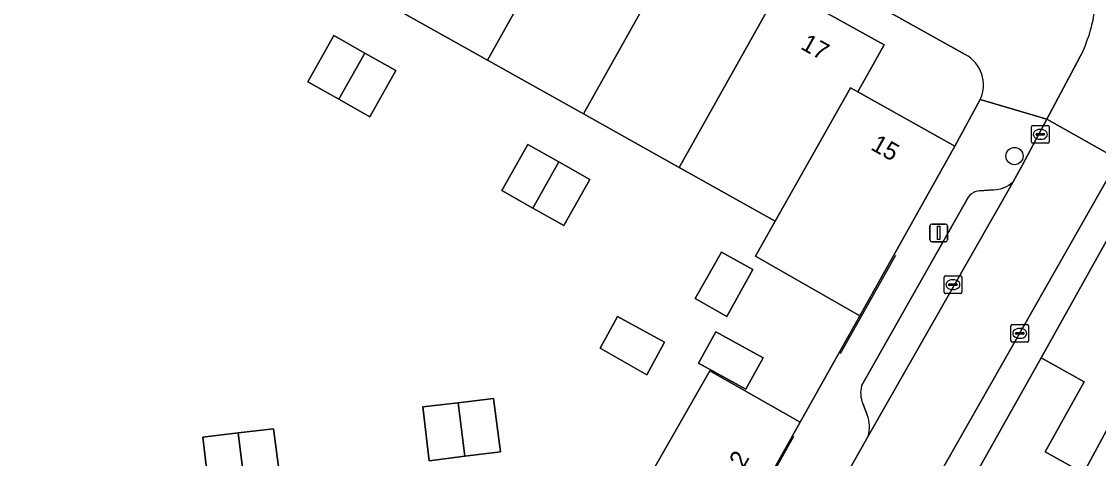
# Model space of a CAD drawing. Extents: x 163147 to 163550, y 380933 to 381639.
# Drawn here: x 163352.5 to 163413.5, y 381516.7 to 381541.5 of the extents above; entities that cross this region are included whole.
import ezdxf

# ---------------------------------------------------------------- set-up
doc = ezdxf.new("R2010")
doc.units = 0
for name, color, linetype in [('IMGEO_Boom', 7, 'Continuous'), ('IMGEO_Erf', 7, 'Continuous'), ('IMGEO_Groenvoorziening', 7, 'Continuous'), ('IMGEO_Kolk', 7, 'Continuous'), ('IMGEO_Lichtmast', 7, 'Continuous'), ('IMGEO_Muur', 7, 'Continuous'), ('IMGEO_Pand', 7, 'Continuous'), ('IMGEO_Pand_nummerreeks', 7, 'Continuous'), ('IMGEO_Parkeervlak_open', 7, 'Continuous'), ('IMGEO_Rijbaan_lokaal_open', 7, 'Continuous'), ('IMGEO_Voetpad_open', 7, 'Continuous')]:
    doc.layers.add(name, color=color, linetype=linetype)

msp = doc.modelspace()

# ---------------------------------------------------------------- linework, layer by layer
at = {"layer": 'IMGEO_Boom'}
msp.add_circle((163408.762, 381533.873), 0.489, dxfattribs=at)
at = {"layer": 'IMGEO_Erf'}
for points in [[(163389.772, 381533.219), (163384.335, 381536.26), (163378.897, 381539.301), (163373.46, 381542.342), (163368.022, 381545.383), (163362.584, 381548.424), (163357.147, 381551.465), (163351.494, 381554.627), (163344.686, 381558.434), (163341.996, 381559.951), (163335.192, 381563.765), (163329.483, 381566.965), (163323.994, 381570.042), (163318.505, 381573.12), (163313.016, 381576.197), (163307.526, 381579.274), (163306.339, 381577.158), (163301.172, 381580.046), (163302.358, 381582.169), (163302.037, 381582.351), (163296.548, 381585.428), (163291.473, 381588.273)], [(163290.692, 381502.077), (163296.934, 381502.909), (163303.175, 381503.742), (163309.37, 381504.568), (163317.378, 381505.636), (163320.439, 381506.043), (163328.504, 381507.143), (163334.606, 381507.974), (163340.83, 381508.823), (163347.054, 381509.671), (163353.278, 381510.52), (163359.502, 381511.368), (163365.726, 381512.217), (163371.951, 381513.065), (163378.25, 381513.924), (163378.437, 381512.446), (163386.81, 381513.506), (163391.494, 381521.713), (163396.616, 381518.793), (163399.995, 381524.821), (163394.095, 381528.2), (163395.21, 381530.178), (163389.772, 381533.219)], [(163412.675, 381515.904), (163410.492, 381517.121), (163412.7, 381521.08), (163410.272, 381522.434), (163405.156, 381513.335)]]:
    msp.add_lwpolyline(points, dxfattribs=at)
for points in [[(163368.718, 381538.086), (163370.193, 381540.698), (163371.952, 381539.705), (163373.711, 381538.712), (163372.236, 381536.1), (163370.477, 381537.093)], [(163381.187, 381534.535), (163382.946, 381533.542), (163384.705, 381532.549), (163383.23, 381529.937), (163381.471, 381530.93), (163379.712, 381531.923)], [(163392.157, 381528.422), (163393.933, 381527.438), (163392.466, 381524.79), (163390.677, 381525.803)], [(163386.277, 381524.781), (163388.941, 381523.333), (163387.936, 381521.476), (163385.288, 381522.981)], [(163390.856, 381522.148), (163391.845, 381523.923), (163394.528, 381522.435), (163393.543, 381520.66)], [(163377.237, 381519.9), (163379.244, 381520.135), (163379.639, 381517.124), (163377.621, 381516.869), (163375.602, 381516.613), (163375.235, 381519.665)], [(163364.781, 381518.185), (163366.788, 381518.42), (163367.183, 381515.409), (163365.165, 381515.154), (163363.146, 381514.898), (163362.779, 381517.95)]]:
    msp.add_lwpolyline(points, close=True, dxfattribs=at)
at = {"layer": 'IMGEO_Groenvoorziening'}
for points in [[(163405.961, 381539.624), (163371.092, 381559.098), (163297.645, 381600.322)], [(163349.497, 381567.024), (163356.3, 381563.209), (163357.48, 381562.547), (163358.512, 381564.182), (163362.881, 381561.73), (163362.519, 381561.082), (163367.958, 381558.033), (163373.393, 381554.987), (163378.828, 381551.941), (163384.263, 381548.895), (163389.698, 381545.85), (163395.133, 381542.804), (163396.436, 381542.073), (163396.812, 381542.714), (163401.373, 381540.169), (163399.878, 381537.517), (163405.373, 381534.442), (163406.822, 381537.075)]]:
    msp.add_lwpolyline(points, dxfattribs=at)
msp.add_arc((163405.063, 381537.901), 1.943, 334.8576, 62.47023, dxfattribs=at)
at = {"layer": 'IMGEO_Kolk'}
for p, q in [((163409.724, 381534.676), (163409.724, 381535.528)), ((163409.799, 381535.602), (163410.651, 381535.602)), ((163410.212, 381535.382), (163410.237, 381535.382)), ((163410.725, 381535.528), (163410.725, 381534.676)), ((163409.983, 381535.096), (163409.983, 381535.108)), ((163410.421, 381535.059), (163410.023, 381535.059)), ((163410.026, 381535.145), (163410.424, 381535.145)), ((163410.235, 381534.822), (163410.21, 381534.822)), ((163410.467, 381535.108), (163410.467, 381535.096)), ((163410.651, 381534.602), (163409.799, 381534.602)), ((163404.772, 381526.162), (163404.772, 381527.014)), ((163404.847, 381527.088), (163405.699, 381527.088)), ((163405.26, 381526.868), (163405.285, 381526.868)), ((163405.773, 381527.014), (163405.773, 381526.162)), ((163405.031, 381526.582), (163405.031, 381526.594)), ((163405.469, 381526.545), (163405.071, 381526.545)), ((163405.074, 381526.631), (163405.472, 381526.631)), ((163405.283, 381526.308), (163405.258, 381526.308)), ((163405.515, 381526.594), (163405.515, 381526.582)), ((163405.699, 381526.088), (163404.847, 381526.088)), ((163408.561, 381523.401), (163408.561, 381524.253)), ((163408.636, 381524.327), (163409.488, 381524.327)), ((163408.82, 381523.821), (163408.82, 381523.833)), ((163409.258, 381523.784), (163408.86, 381523.784)), ((163408.863, 381523.87), (163409.261, 381523.87)), ((163409.049, 381524.107), (163409.074, 381524.107)), ((163409.304, 381523.833), (163409.304, 381523.821)), ((163409.562, 381524.253), (163409.562, 381523.401)), ((163409.488, 381523.327), (163408.636, 381523.327)), ((163409.072, 381523.547), (163409.047, 381523.547))]:
    msp.add_line(p, q, dxfattribs=at)
for points in [[(163409.724, 381534.676), (163409.724, 381535.528)], [(163409.799, 381535.602), (163410.651, 381535.602)], [(163410.725, 381535.528), (163410.725, 381534.676)], [(163410.651, 381534.602), (163409.799, 381534.602)], [(163404.772, 381526.162), (163404.772, 381527.014)], [(163404.847, 381527.088), (163405.699, 381527.088)], [(163405.773, 381527.014), (163405.773, 381526.162)], [(163405.699, 381526.088), (163404.847, 381526.088)], [(163408.561, 381523.401), (163408.561, 381524.253)], [(163408.636, 381524.327), (163409.488, 381524.327)], [(163409.562, 381524.253), (163409.562, 381523.401)], [(163409.488, 381523.327), (163408.636, 381523.327)]]:
    msp.add_lwpolyline(points, dxfattribs=at)
for centre, radius, start, end in [((163409.801, 381535.526), 0.0765, 91.55205, 178.44795), ((163409.801, 381535.526), 0.0765, 91.55205, 178.44795), ((163410.649, 381535.526), 0.0765, 1.55205, 88.44795), ((163410.649, 381535.526), 0.0765, 1.55205, 88.44795), ((163410.023, 381535.105), 0.0403, 85.87752, 175.75265), ((163410.02, 381535.095), 0.0366, 178.93798, 274.71019), ((163410.424, 381535.102), 0.043, 264.86636, 352.45326), ((163410.428, 381535.107), 0.0386, 1.73085, 96.63898), ((163409.801, 381534.678), 0.0765, 181.55205, 268.44795), ((163409.801, 381534.678), 0.0765, 181.55205, 268.44795), ((163410.649, 381534.678), 0.0765, 271.55205, 358.44795), ((163410.649, 381534.678), 0.0765, 271.55205, 358.44795), ((163404.849, 381527.012), 0.0765, 91.55205, 178.44795), ((163404.849, 381527.012), 0.0765, 91.55205, 178.44795), ((163405.697, 381527.012), 0.0765, 1.55205, 88.44795), ((163405.697, 381527.012), 0.0765, 1.55205, 88.44795), ((163405.071, 381526.591), 0.0403, 85.87752, 175.75265), ((163405.068, 381526.581), 0.0366, 178.93798, 274.71019), ((163405.472, 381526.588), 0.043, 264.86636, 352.45326), ((163405.476, 381526.593), 0.0386, 1.73085, 96.63898), ((163404.849, 381526.164), 0.0765, 181.55205, 268.44795), ((163404.849, 381526.164), 0.0765, 181.55205, 268.44795), ((163405.697, 381526.164), 0.0765, 271.55205, 358.44795), ((163405.697, 381526.164), 0.0765, 271.55205, 358.44795), ((163408.638, 381524.251), 0.0765, 91.55205, 178.44795), ((163408.638, 381524.251), 0.0765, 91.55205, 178.44795), ((163408.86, 381523.83), 0.0403, 85.87752, 175.75265), ((163408.857, 381523.82), 0.0366, 178.93798, 274.71019), ((163409.261, 381523.827), 0.043, 264.86636, 352.45326), ((163409.265, 381523.832), 0.0386, 1.73085, 96.63898), ((163409.486, 381524.251), 0.0765, 1.55205, 88.44795), ((163409.486, 381524.251), 0.0765, 1.55205, 88.44795), ((163408.638, 381523.403), 0.0765, 181.55205, 268.44795), ((163408.638, 381523.403), 0.0765, 181.55205, 268.44795), ((163409.486, 381523.403), 0.0765, 271.55205, 358.44795), ((163409.486, 381523.403), 0.0765, 271.55205, 358.44795)]:
    msp.add_arc(centre, radius, start, end, dxfattribs=at)
for centre, major_axis, ratio, start_param, end_param in [((163410.211, 381535.102), (-0.387, 0.002), 0.722429, 4.712389, 7.853982), ((163410.236, 381535.102), (-0.39, 0.002), 0.717154, 1.570796, 4.712389), ((163405.259, 381526.588), (-0.387, 0.002), 0.722429, 4.712389, 7.853982), ((163405.284, 381526.588), (-0.39, 0.002), 0.717154, 1.570796, 4.712389), ((163409.048, 381523.827), (-0.387, 0.002), 0.722429, 4.712389, 7.853982), ((163409.073, 381523.827), (-0.39, 0.002), 0.717154, 1.570796, 4.712389)]:
    msp.add_ellipse(centre, major_axis=major_axis, ratio=ratio, start_param=start_param, end_param=end_param, dxfattribs=at)
at = {"layer": 'IMGEO_Lichtmast'}
for p, q in [((163403.97, 381529.119), (163403.97, 381529.919)), ((163403.97, 381529.919), (163403.97, 381529.119)), ((163404.07, 381530.019), (163404.86, 381530.019)), ((163404.86, 381530.019), (163404.07, 381530.019)), ((163404.96, 381529.919), (163404.96, 381529.119)), ((163404.96, 381529.119), (163404.96, 381529.919)), ((163404.86, 381529.019), (163404.07, 381529.019)), ((163404.07, 381529.019), (163404.86, 381529.019))]:
    msp.add_line(p, q, dxfattribs=at)
msp.add_lwpolyline([(163404.39, 381529.894), (163404.54, 381529.894), (163404.54, 381529.144), (163404.39, 381529.144), (163404.39, 381529.894)], dxfattribs=at)
for centre, start, end in [((163404.07, 381529.919), 90, 180), ((163404.07, 381529.919), 90, 180), ((163404.86, 381529.919), 0, 90), ((163404.86, 381529.919), 360, 90), ((163404.07, 381529.119), 180, 270), ((163404.07, 381529.119), 180, 270), ((163404.86, 381529.119), 270, 0), ((163404.86, 381529.119), 270, 0)]:
    msp.add_arc(centre, 0.1, start, end, dxfattribs=at)
at = {"layer": 'IMGEO_Muur'}
for points in [[(163398.9, 381522.691), (163402.034, 381528.266)], [(163405.156, 381513.335), (163410.272, 381522.434)], [(163394.422, 381514.725), (163396.264, 381518.003)]]:
    msp.add_lwpolyline(points, dxfattribs=at)
at = {"layer": 'IMGEO_Pand'}
for points in [[(163384.263, 381548.895), (163378.828, 381551.941), (163373.46, 381542.342), (163378.897, 381539.301)], [(163389.698, 381545.85), (163384.263, 381548.895), (163378.897, 381539.301), (163384.335, 381536.26)], [(163395.133, 381542.804), (163389.698, 381545.85), (163384.335, 381536.26), (163389.772, 381533.219)], [(163399.474, 381537.743), (163399.878, 381537.517), (163401.373, 381540.169), (163396.812, 381542.714), (163396.436, 381542.073), (163395.133, 381542.804), (163389.772, 381533.219), (163395.21, 381530.178)], [(163371.952, 381539.705), (163370.193, 381540.698), (163368.718, 381538.086), (163370.477, 381537.093)], [(163373.711, 381538.712), (163371.952, 381539.705), (163370.477, 381537.093), (163372.236, 381536.1)], [(163405.373, 381534.442), (163399.878, 381537.517), (163399.474, 381537.743), (163395.21, 381530.178), (163394.095, 381528.2), (163399.995, 381524.821)], [(163382.946, 381533.542), (163381.187, 381534.535), (163379.712, 381531.923), (163381.471, 381530.93)], [(163384.705, 381532.549), (163382.946, 381533.542), (163381.471, 381530.93), (163383.23, 381529.937)], [(163412.675, 381515.904), (163418.679, 381527.058), (163414.231, 381529.537), (163410.272, 381522.434), (163412.7, 381521.08), (163410.492, 381517.121)], [(163418.679, 381527.058), (163412.675, 381515.904), (163414.86, 381514.686), (163415.352, 381514.411), (163418.659, 381520.343), (163421.229, 381518.91), (163425.443, 381526.737), (163420.55, 381529.464), (163419.083, 381526.833)], [(163393.933, 381527.438), (163392.157, 381528.422), (163390.677, 381525.803), (163392.466, 381524.79)], [(163387.936, 381521.476), (163388.941, 381523.333), (163386.277, 381524.781), (163385.288, 381522.981)], [(163390.856, 381522.148), (163393.543, 381520.66), (163394.528, 381522.435), (163391.845, 381523.923)], [(163396.616, 381518.793), (163391.494, 381521.713), (163386.81, 381513.506), (163390.622, 381508.099)], [(163377.237, 381519.9), (163377.621, 381516.869), (163379.639, 381517.124), (163379.244, 381520.135)], [(163377.237, 381519.9), (163375.235, 381519.665), (163375.602, 381516.613), (163377.621, 381516.869)], [(163364.781, 381518.185), (163365.165, 381515.154), (163367.183, 381515.409), (163366.788, 381518.42)], [(163364.781, 381518.185), (163362.779, 381517.95), (163363.146, 381514.898), (163365.165, 381515.154)]]:
    msp.add_lwpolyline(points, close=True, dxfattribs=at)
at = {"layer": 'IMGEO_Parkeervlak_open'}
for points in [[(163400.477, 381518.009), (163408.677, 381532.42)], [(163407.579, 381531.958), (163406.779, 381531.908)], [(163406.154, 381531.56), (163400.091, 381520.848)], [(163400.164, 381519.848), (163400.416, 381519.211)]]:
    msp.add_lwpolyline(points, dxfattribs=at)
for centre, radius, start, end in [((163407.491, 381533.704), 1.748, 272.89651, 312.7428), ((163406.875, 381531), 0.913, 96.05823, 142.15989), ((163401.659, 381520.46), 1.615, 166.09487, 202.2555), ((163398.581, 381518.515), 1.963, 345.0495, 20.7609)]:
    msp.add_arc(centre, radius, start, end, dxfattribs=at)
at = {"layer": 'IMGEO_Rijbaan_lokaal_open'}
msp.add_lwpolyline([(163412.47, 381539.47), (163410.599, 381535.956), (163414.654, 381533.678), (163416.384, 381536.72), (163416.546, 381536.957), (163416.871, 381537.519)], dxfattribs=at)
msp.add_lwpolyline([(163414.262, 381532.989), (163414.654, 381533.678), (163410.599, 381535.956), (163409.219, 381533.373), (163408.677, 381532.42), (163400.477, 381518.009), (163399.217, 381515.793), (163392.697, 381504.335), (163396.678, 381502.07), (163399.031, 381506.208), (163400.059, 381508.016), (163402.013, 381511.452), (163403.04, 381513.257)], close=True, dxfattribs=at)
msp.add_arc((163404.639, 381543.411), 8.767, 333.28212, 352.70329, dxfattribs=at)
at = {"layer": 'IMGEO_Voetpad_open'}
for points in [[(163299.241, 381609.999), (163298.734, 381610.132), (163298.144, 381610.261), (163292.447, 381605.644), (163291.519, 381603.953), (163297.645, 381600.322), (163371.092, 381559.098), (163405.961, 381539.624)], [(163406.822, 381537.075), (163410.599, 381535.956), (163412.47, 381539.47)], [(163408.677, 381532.42), (163409.219, 381533.373), (163410.599, 381535.956), (163406.822, 381537.075), (163405.373, 381534.442), (163399.995, 381524.821), (163396.616, 381518.793), (163390.622, 381508.099), (163386.878, 381501.46), (163386.472, 381497.48)], [(163414.231, 381529.537), (163415.715, 381532.175), (163417.612, 381535.547), (163416.384, 381536.72), (163414.654, 381533.678), (163414.262, 381532.989), (163403.04, 381513.257), (163402.013, 381511.452), (163400.059, 381508.016), (163399.031, 381506.208), (163396.678, 381502.07), (163395.5, 381500)], [(163406.779, 381531.908), (163407.579, 381531.958)], [(163400.091, 381520.848), (163406.154, 381531.56)], [(163393.804, 381490.754), (163396.932, 381490.11), (163399.443, 381490.376), (163402.139, 381490.739), (163401.915, 381492.238), (163401.169, 381497.642), (163400.844, 381500), (163400.424, 381503.043), (163400.279, 381504.213), (163400.246, 381504.532), (163404.666, 381512.456), (163405.156, 381513.335), (163410.272, 381522.434), (163414.231, 381529.537)], [(163400.416, 381519.211), (163400.164, 381519.848)], [(163399.217, 381515.793), (163400.477, 381518.009)]]:
    msp.add_lwpolyline(points, dxfattribs=at)
for centre, radius, start, end in [((163404.639, 381543.411), 8.767, 333.28212, 352.70329), ((163405.063, 381537.901), 1.943, 334.8576, 62.47023), ((163407.491, 381533.704), 1.748, 272.89651, 312.7428), ((163406.875, 381531), 0.913, 96.05823, 142.15989), ((163401.659, 381520.46), 1.615, 166.09487, 202.2555), ((163398.581, 381518.515), 1.963, 345.0495, 20.7609)]:
    msp.add_arc(centre, radius, start, end, dxfattribs=at)

# ---------------------------------------------------------------- texts
at = {"layer": 'IMGEO_Pand_nummerreeks'}
for s, rotation, p in [('17', 330.83645, (163396.585, 381539.977)), ('15', 330.76769, (163400.557, 381534.273)), ('2', 60.7278, (163393.413, 381516.146))]:
    msp.add_text(s, height=1, rotation=rotation, dxfattribs=at).set_placement(p)

doc.saveas('drawing.dxf')
